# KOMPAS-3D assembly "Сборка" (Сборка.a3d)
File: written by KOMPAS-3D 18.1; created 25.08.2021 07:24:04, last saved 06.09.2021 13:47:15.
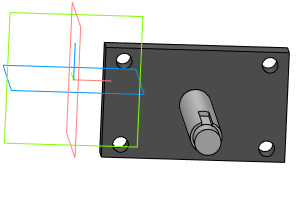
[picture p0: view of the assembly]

Document properties: Автор: 111; Полное имя файла: C:\Users\admin\Desktop\ffb\Сборка.a3d

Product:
- Part/product: Сборка
    Масса: 0.280677
  - Component [detail]: Деталь  | Масса: 0.0680655; source file: 10.m3d
  - Component [detail]: Деталь  | Масса: 0.212612; Форматы листов документа: A4; source file: 2.m3d, 7.cdw

Referenced files in C:\Users\admin\Desktop\ffb\: 10.m3d, 2.m3d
